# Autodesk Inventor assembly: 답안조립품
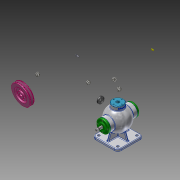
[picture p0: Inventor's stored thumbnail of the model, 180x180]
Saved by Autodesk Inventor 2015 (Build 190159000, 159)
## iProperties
Created: 2025-08
Part Number: 답안조립품
Document SubType Name: Assembly
Designer: user
Author: user
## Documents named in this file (14)
- C:\Users\user\Desktop\750808V1003\답안조립품.iam
- C:\Users\user\Desktop\750808V1003\본체.ipt
- C:\Users\user\Desktop\750808V1003\가져온 구성요소\V-벨트풀리\V-벨트풀리.ipt
- C:\Users\user\Desktop\750808V1003\가져온 구성요소\너트 M8\너트 M8.ipt
- C:\Users\user\Desktop\750808V1003\가져온 구성요소\뒤커버\뒤커버.ipt
- C:\Users\user\Desktop\750808V1003\가져온 구성요소\베어링- 6202\베어링- 6202.ipt
- C:\Users\user\Desktop\750808V1003\가져온 구성요소\볼트 M4 x 12\볼트 M4 x 12.ipt
- C:\Users\user\Desktop\750808V1003\가져온 구성요소\볼트 M4 x 16\볼트 M4 x 16.ipt
- C:\Users\user\Desktop\750808V1003\가져온 구성요소\상부커버\상부커버.ipt
- C:\Users\user\Desktop\750808V1003\가져온 구성요소\앞커버\앞커버.ipt
- C:\Users\user\Desktop\750808V1003\가져온 구성요소\오일실 15 30 7\오일실 15 30 7.ipt
- C:\Users\user\Desktop\750808V1003\가져온 구성요소\칼라\칼라.ipt
- C:\Users\user\Desktop\750808V1003\가져온 구성요소\키 4 x 4 x 12\키 4 x 4 x 12.ipt
- C:\Users\user\Desktop\750808V1003\가져온 구성요소\편심축\편심축.ipt
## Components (1 placed, 1 different names)
1. V-벨트풀리:1
